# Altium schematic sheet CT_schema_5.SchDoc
size 218 x 258 mm
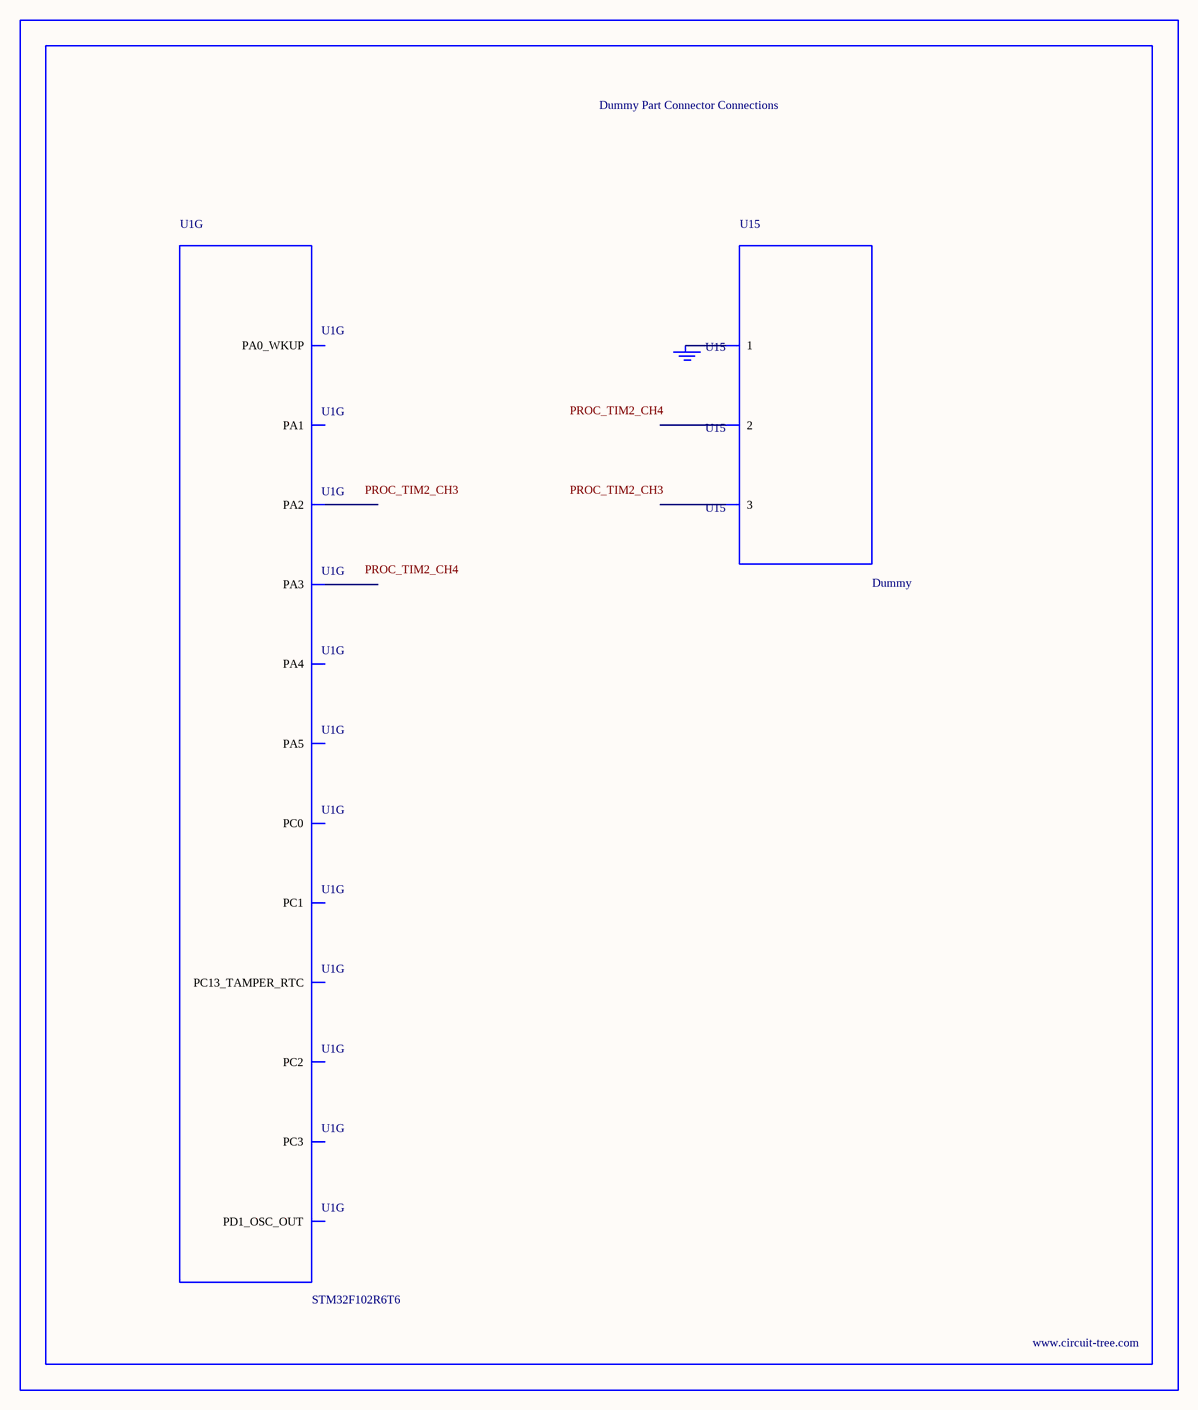
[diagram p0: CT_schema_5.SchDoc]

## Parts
BORDER4  (no value)
GND_INSTANCE_4_0  (no value)
U1  STM32F102R6T6  [LQFP64]  (part G of 7)
U15  Dummy  [DUMMY_PACKAGE_146]

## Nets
NetGND_INSTANCE_4_0_0: GND_INSTANCE_4_0.0(GND) U15.1

Not connected (* = marked no-connect by the designer): U1 2(PC13_TAMPER_RTC) 6(PD1_OSC_OUT) 8(PC0) 9(PC1) 10(PC2) 11(PC3) 14(PA0_WKUP) 15(PA1) 16(PA2) 17(PA3) 20(PA4) 21(PA5); U15 2 3

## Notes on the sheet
- Labels drawn without touching a wire or pin: PROC_TIM2_CH3, PROC_TIM2_CH4

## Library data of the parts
BORDER4 = BORDER_PAGE4
GND_INSTANCE_4_0 = GND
